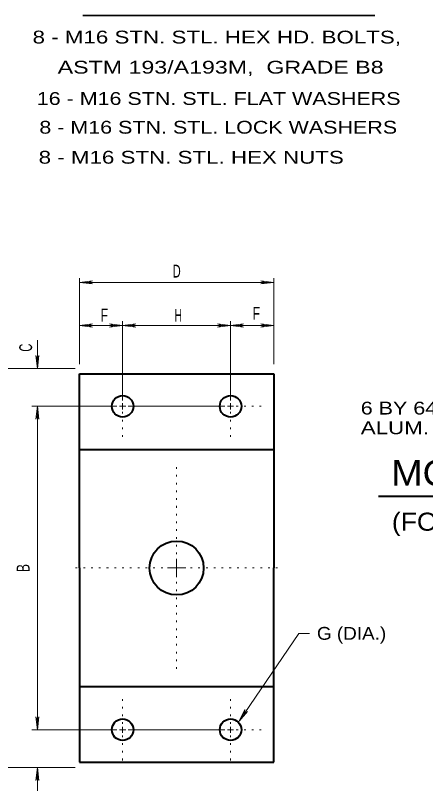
# Model space of a CAD drawing. Extents: x 312583 to 312854, y 144419 to 144597.
# Drawn here: x 312664.19 to 312688.47, y 144489.79 to 144535.32 of the extents above; entities that cross this region are included whole.
import ezdxf
from ezdxf.enums import TextEntityAlignment as Align

# ---------------------------------------------------------------- set-up
doc = ezdxf.new("R2010")
doc.units = 0
doc.header["$LTSCALE"] = 0.3
doc.linetypes.add('DOTTED', pattern=[1.5, 0.3, -1.2])
doc.layers.add('1', color=7, linetype='Continuous', lineweight=40)

msp = doc.modelspace()

# ---------------------------------------------------------------- linework, layer by layer
at = {"layer": '1', "lineweight": 35}
msp.add_line((312668.1763, 144535.3213), (312685.4687, 144535.3213), dxfattribs=at)
at = {"layer": '1', "lineweight": 13}
for p, q in [((312667.9837, 144514.6463), (312667.9837, 144519.7523)), ((312667.9837, 144519.4993), (312668.7504, 144519.5913)), ((312668.7504, 144519.5913), (312668.5051, 144519.4993)), ((312678.7171, 144519.5913), (312678.9624, 144519.4993)), ((312679.4837, 144519.4993), (312678.7171, 144519.5913)), ((312679.4837, 144514.6463), (312679.4837, 144519.7523)), ((312667.9837, 144519.4993), (312679.4837, 144519.4993)), ((312667.9837, 144519.4993), (312668.7504, 144519.4073)), ((312668.7504, 144519.4073), (312668.5051, 144519.4993)), ((312678.7171, 144519.4073), (312678.9624, 144519.4993)), ((312679.4837, 144519.4993), (312678.7171, 144519.4073)), ((312667.9837, 144516.9463), (312668.7504, 144517.0383)), ((312670.5367, 144516.9463), (312667.9837, 144516.9463)), ((312667.9837, 144516.9463), (312668.7504, 144516.8466)), ((312668.7504, 144517.0383), (312668.5051, 144516.9463)), ((312668.7504, 144516.8466), (312668.5051, 144516.9463)), ((312669.7701, 144517.0383), (312670.0154, 144516.9463)), ((312670.5367, 144516.9463), (312669.7701, 144517.0383)), ((312669.7701, 144516.8466), (312670.0154, 144516.9463)), ((312670.5367, 144516.9463), (312669.7701, 144516.8466)), ((312670.5367, 144512.492), (312670.5367, 144517.1993)), ((312670.5367, 144516.9463), (312671.3111, 144517.0383)), ((312676.9307, 144516.9463), (312670.5367, 144516.9463)), ((312670.5367, 144516.9463), (312671.3111, 144516.8466)), ((312671.3111, 144517.0383), (312671.0657, 144516.9463)), ((312671.3111, 144516.8466), (312671.0657, 144516.9463)), ((312676.1564, 144517.0383), (312676.4017, 144516.9463)), ((312676.9307, 144516.9463), (312676.1564, 144517.0383)), ((312676.1564, 144516.8466), (312676.4017, 144516.9463)), ((312676.9307, 144516.9463), (312676.1564, 144516.8466)), ((312676.9307, 144512.492), (312676.9307, 144517.1993)), ((312676.9307, 144516.9463), (312677.6974, 144517.0383)), ((312679.4837, 144516.9463), (312676.9307, 144516.9463)), ((312676.9307, 144516.9463), (312677.6974, 144516.8466)), ((312677.6974, 144517.0383), (312677.4521, 144516.9463)), ((312677.6974, 144516.8466), (312677.4521, 144516.9463)), ((312678.7171, 144517.0383), (312678.9624, 144516.9463)), ((312679.4837, 144516.9463), (312678.7171, 144517.0383)), ((312678.7171, 144516.8466), (312678.9624, 144516.9463)), ((312679.4837, 144516.9463), (312678.7171, 144516.8466)), ((312665.4921, 144516.0646), (312665.4921, 144514.3856)), ((312665.4001, 144515.16), (312665.4921, 144514.9146)), ((312665.4921, 144514.3856), (312665.4001, 144515.16)), ((312665.5841, 144515.16), (312665.4921, 144514.9146)), ((312665.4921, 144514.3856), (312665.5841, 144515.16)), ((312667.7307, 144514.3856), (312662.6171, 144514.3856)), ((312670.5367, 144512.1546), (312670.5367, 144512.331)), ((312676.9307, 144512.1546), (312676.9307, 144512.331)), ((312670.1994, 144512.1546), (312665.1701, 144512.1546)), ((312665.4921, 144512.1546), (312665.4001, 144511.3803)), ((312665.4921, 144512.1546), (312665.5841, 144511.3803)), ((312665.4921, 144492.988), (312665.4921, 144512.1546)), ((312670.5367, 144512.1546), (312670.3604, 144512.1546)), ((312670.5367, 144512.1546), (312670.7207, 144512.1546)), ((312670.5367, 144512.1546), (312670.5367, 144511.9706)), ((312670.8741, 144512.1546), (312676.5934, 144512.1546)), ((312676.9307, 144512.1546), (312676.7467, 144512.1546)), ((312676.9307, 144512.1546), (312677.1071, 144512.1546)), ((312676.9307, 144512.1546), (312676.9307, 144511.9706)), ((312665.4001, 144511.3803), (312665.4921, 144511.6256)), ((312665.5841, 144511.3803), (312665.4921, 144511.6256)), ((312673.7337, 144502.5713), (312673.7337, 144503.1156)), ((312673.7337, 144502.5713), (312673.1894, 144502.5713)), ((312673.7337, 144502.5713), (312674.2781, 144502.5713)), ((312673.7337, 144502.5713), (312673.7337, 144502.0193)), ((312677.4291, 144493.4863), (312680.9711, 144498.692)), ((312680.9711, 144498.692), (312681.6074, 144498.692)), ((312677.4291, 144493.4863), (312677.7817, 144494.1763)), ((312677.4291, 144493.4863), (312677.9351, 144494.069)), ((312677.7817, 144494.1763), (312677.7204, 144493.9156)), ((312677.9351, 144494.069), (312677.7204, 144493.9156)), ((312665.4001, 144493.7546), (312665.4921, 144493.5093)), ((312665.4921, 144492.988), (312665.4001, 144493.7546)), ((312665.5841, 144493.7546), (312665.4921, 144493.5093)), ((312665.4921, 144492.988), (312665.5841, 144493.7546)), ((312670.5367, 144492.988), (312670.5367, 144493.1643)), ((312676.9307, 144492.988), (312676.9307, 144493.1643)), ((312670.1994, 144492.988), (312665.1701, 144492.988)), ((312670.5367, 144492.988), (312670.3604, 144492.988)), ((312670.5367, 144492.988), (312670.7207, 144492.988)), ((312670.5367, 144492.988), (312670.5367, 144492.804)), ((312670.8741, 144492.988), (312676.5934, 144492.988)), ((312676.9307, 144492.988), (312676.7467, 144492.988)), ((312676.9307, 144492.988), (312677.1071, 144492.988)), ((312676.9307, 144492.988), (312676.9307, 144492.804)), ((312667.7307, 144490.7493), (312662.6171, 144490.7493)), ((312665.4921, 144490.7493), (312665.4001, 144489.9826)), ((312665.4921, 144488.9706), (312665.4921, 144490.7493)), ((312665.4921, 144490.7493), (312665.5841, 144489.9826)), ((312665.4001, 144489.9826), (312665.4921, 144490.228)), ((312665.5841, 144489.9826), (312665.4921, 144490.228))]:
    msp.add_line(p, q, dxfattribs=at)
at = {"layer": '1'}
for p, q in [((312667.9837, 144514.0713), (312679.4837, 144514.0713)), ((312667.9837, 144502.5713), (312667.9837, 144514.0713)), ((312679.4837, 144514.0713), (312679.4837, 144502.5713)), ((312667.9837, 144509.594), (312679.4837, 144509.594)), ((312685.6759, 144506.8265), (312716.0085, 144506.8265)), ((312667.9837, 144502.5713), (312667.9837, 144491.0713)), ((312679.4837, 144491.0713), (312679.4837, 144502.5713)), ((312667.9837, 144495.541), (312679.4837, 144495.541)), ((312667.9837, 144491.0713), (312679.4837, 144491.0713))]:
    msp.add_line(p, q, dxfattribs=at)
at = {"layer": '1', "linetype": 'DOTTED', "lineweight": 13}
for p, q in [((312670.1994, 144512.1546), (312668.7964, 144512.1546)), ((312670.5367, 144511.8173), (312670.5367, 144510.0616)), ((312676.9307, 144511.8173), (312676.9307, 144510.0616)), ((312677.2681, 144512.1546), (312679.0161, 144512.1546)), ((312673.7337, 144503.384), (312673.7337, 144508.835)), ((312672.9134, 144502.5713), (312667.4624, 144502.5713)), ((312674.5541, 144502.5713), (312680.0051, 144502.5713)), ((312673.7337, 144501.751), (312673.7337, 144496.3)), ((312670.5367, 144493.3253), (312670.5367, 144495.0733)), ((312676.9307, 144493.3253), (312676.9307, 144495.0733)), ((312677.2681, 144492.988), (312679.0161, 144492.988)), ((312670.5367, 144492.6506), (312670.5367, 144490.895)), ((312676.9307, 144492.6506), (312676.9307, 144490.895))]:
    msp.add_line(p, q, dxfattribs=at)
at = {"layer": '1'}
for centre, radius in [((312670.5393, 144512.1521), 0.6389), ((312676.9282, 144512.1521), 0.6389), ((312673.7337, 144502.5687), 1.5972), ((312670.5393, 144492.9854), 0.6389), ((312676.9282, 144492.9854), 0.6389)]:
    msp.add_circle(centre, radius, dxfattribs=at)

# ---------------------------------------------------------------- texts
for s, width, p in [(' 8 - M16 STN. STL. HEX HD. BOLTS,', 1.3, (312664.8422, 144533.654)), ('     ASTM 193/A193M,  GRADE B8', 1.35, (312664.7886, 144531.8677)), ('16 - M16 STN. STL. FLAT WASHERS', 1.25, (312665.4577, 144530.0123)), (' 8 - M16 STN. STL. LOCK WASHERS', 1.25, (312665.2562, 144528.3103)), (' 8 - M16 STN. STL. HEX NUTS', 1.3, (312665.2026, 144526.5317)), ('D', 0.65, (312673.5003, 144519.7839)), ('F', 0.7, (312669.2409, 144517.1777)), ('H', 0.6, (312673.6129, 144517.16)), ('F', 0.7, (312678.2391, 144517.2841)), ('6 BY 64 MM BAR CLAMP', 1.25, (312684.6356, 144511.6659)), ('ALUM. AL. 6063-T6', 1.3, (312684.6356, 144510.4996)), ('G (DIA.)', 1.1, (312682.0401, 144498.3154))]:
    msp.add_text(s, height=0.76, dxfattribs=dict(at, width=width)).set_placement(p)
for s, width, p in [('C', 0.65, (312665.1812, 144515.3885)), ('B', 0.7, (312665.0308, 144502.3293))]:
    msp.add_text(s, height=0.76, rotation=90, dxfattribs=dict(at, width=width)).set_placement(p)
at = {"layer": '1', "width": 1.1}
for s, height, p in [('MOUNTING STRAP DETAIL', 1.52, (312700.7824, 144507.4408)), ('(FOR ALTERNATE MOUNTING STRAP', 1.07, (312700.5946, 144504.7794))]:
    msp.add_text(s, height=height, dxfattribs=at).set_placement(p, align=Align.CENTER)

doc.saveas('drawing.dxf')
